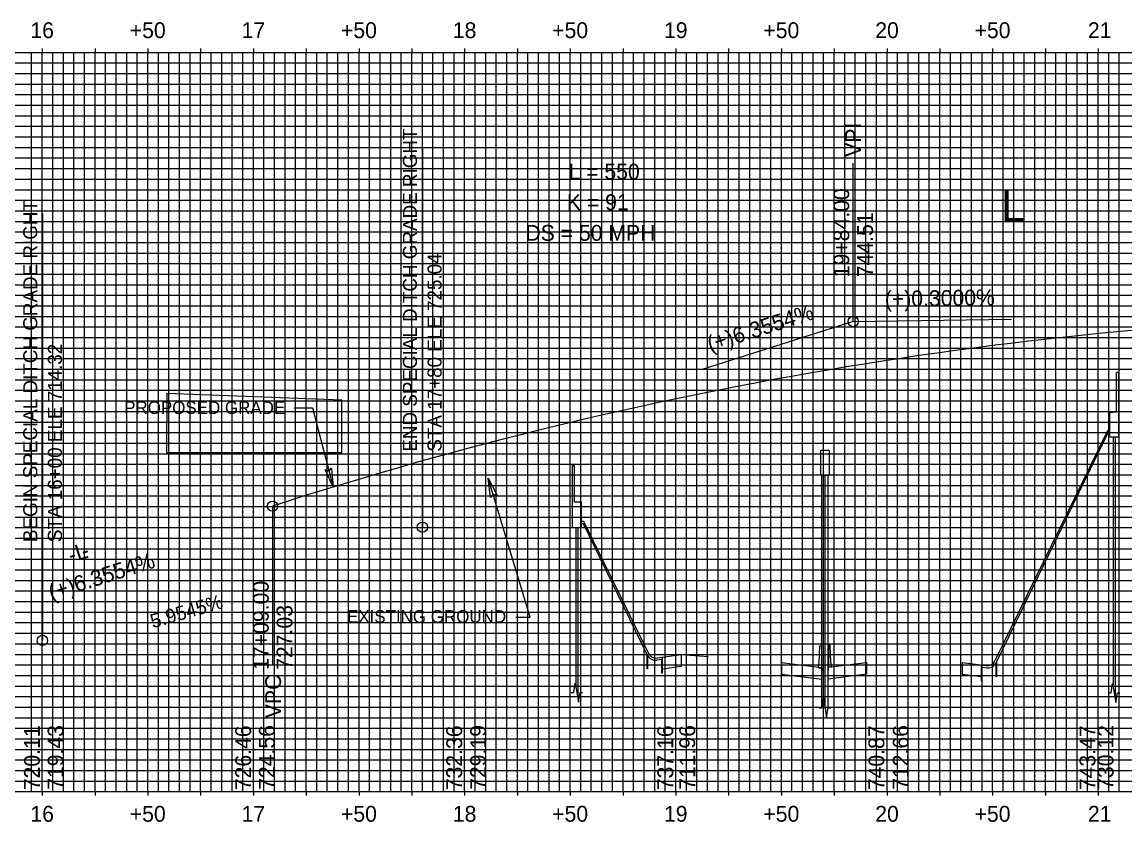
# Model space of a CAD drawing. Extents: x 273 to 1727, y 687 to 1144.
# Drawn here: x 590 to 1113, y 766 to 1144 of the extents above; entities that cross this region are included whole.
import ezdxf

# ---------------------------------------------------------------- set-up
doc = ezdxf.new("R2010")
doc.units = 0
for name, color, linetype in [('3D Cell Connection Region', 7, 'Continuous'), ('Catch Basin Box 24 Dia-Bottom CELL', 7, 'Continuous'), ('Construction Elements LEVEL', 7, 'Continuous'), ('Cut Ditch Special with Hinge Detail CELL', 7, 'Continuous'), ('Default', 7, 'Continuous'), ('Drop Inlet Box Type A 48 Dia-Bottom CELL', 7, 'Continuous'), ('Drop Inlet Box Type B 36 Dia-Bottom CELL', 7, 'Continuous'), ('Drop Inlet Grate 2 Narrow Slot and Flat Grates 840 29 36 Dia BD CELL', 7, 'Continuous'), ('Drop Inlet Grate 2 Narrow Slot and Flat Grates 840 29 36 Dia BD-Top CELL', 7, 'Continuous'), ('Drop Inlet Grate 2 Narrow Slot and Flat Grates 840 29 36 Dia TB-Top CELL', 7, 'Continuous'), ('Drop Inlet Grate 2 Wide Slot and Flat Grates 840 20 48 Dia Apron-Top CELL', 7, 'Continuous'), ('Drop Inlet Grate 2 Wide Slot and Flat Grates 840 20 TB-Top CELL', 7, 'Continuous'), ('E_NCDOT_Terrain_Model_Triangle_Vertices', 7, 'Continuous'), ('E_NCDOT_Vertical_Profile_Ground_Line', 7, 'Continuous'), ('Junction Box with Manhole 840 31 42 Dia TB-Top CELL', 7, 'Continuous'), ('Junction Box with Manhole 840 31 48 Dia CELL', 7, 'Continuous'), ('Junction Box with Manhole 840 31 66 Dia-Top CELL', 7, 'Continuous'), ('Junction Box with Manhole 840 52 Round TB 6 Feet CELL', 7, 'Continuous'), ('P_HYD_Drop_Inlet_Box_Type_B_36_Dia-Bottom_CELL', 7, 'Continuous'), ('P_NCDOT_SS_Cut_Line', 7, 'Continuous'), ('P_NCDOT_SS_Transition_Line', 7, 'Continuous')]:
    doc.layers.add(name, color=color, linetype=linetype)

msp = doc.modelspace()

# ---------------------------------------------------------------- linework, layer by layer
at = {"layer": 'Construction Elements LEVEL'}
for p, q in [((600, 780), (600, 1130)), ((650, 780), (650, 1130)), ((700, 780), (700, 1130)), ((750, 780), (750, 1130)), ((800, 780), (800, 1130)), ((850, 780), (850, 1130)), ((900, 780), (900, 1130)), ((950, 780), (950, 1130)), ((1000, 780), (1000, 1130)), ((1050, 780), (1050, 1130)), ((1100, 780), (1100, 1130)), ((517.06, 1080), (1700, 1080)), ((300, 1030), (1700, 1030)), ((300, 980), (1700, 980)), ((300, 930), (1700, 930)), ((300, 880), (1700, 880)), ((300, 830), (1700, 830)), ((300, 780), (1700, 780)), ((300, 780), (1700, 780))]:
    msp.add_line(p, q, dxfattribs=at)
at = {"layer": 'Cut Ditch Special with Hinge Detail CELL'}
for p, q in [((780, 1084.3), (780, 905.2)), ((600.08, 1053.65), (600.08, 851.6))]:
    msp.add_line(p, q, dxfattribs=at)
for centre in [(780, 905.2), (600.08, 851.6)]:
    msp.add_circle(centre, 2.43, dxfattribs=at)
at = {"layer": 'Default'}
msp.add_arc((1286.54, -872.9), 1879.03, 90.83992, 107.90043, dxfattribs=at)
at = {"layer": 'Drop Inlet Box Type A 48 Dia-Bottom CELL'}
for p, q in [((1108.7, 959.88), (1108.7, 978.45)), ((1109.7, 978.45), (1108.7, 978.45)), ((1109.7, 947.88), (1109.7, 978.45)), ((1105.45, 959.56), (1108.7, 959.88)), ((1105.45, 947.88), (1105.45, 959.56)), ((1105.45, 950.88), (1104.45, 950.88)), ((1105.45, 949.88), (1104.52, 949.88)), ((1109.7, 947.88), (1105.45, 947.88)), ((851.02, 904.98), (851.02, 934.36)), ((851.02, 934.36), (852.02, 934.36)), ((852.02, 916.98), (852.02, 934.36)), ((855.27, 916.98), (852.02, 916.98)), ((855.27, 904.98), (855.27, 916.98)), ((851.02, 904.98), (855.27, 904.98)), ((855.27, 907.98), (856.27, 907.98)), ((855.27, 906.98), (856.2, 906.98))]:
    msp.add_line(p, q, dxfattribs=at)
at = {"layer": 'Drop Inlet Box Type B 36 Dia-Bottom CELL'}
for p, q in [((984, 1002.55), (984, 1077.55)), ((984, 1002.55), (1058.99, 1003.67)), ((984, 1002.55), (912.52, 979.84)), ((984, 1002.55), (984, 1002.55)), ((719.34, 961.77), (727.98, 961.77)), ((727.98, 961.77), (737.83, 924.1)), ((831.04, 862.63), (811.2, 928.36)), ((709, 915.16), (709, 915.16)), ((709, 915.16), (709, 840.16)), ((824.2, 862.63), (831.04, 862.63))]:
    msp.add_line(p, q, dxfattribs=at)
msp.add_lwpolyline([(658.81, 940.58), (741.85, 940.58), (741.85, 965.31), (659.01, 968.57)], close=True, dxfattribs=at)
for centre in [(984, 1002.55), (709, 915.16)]:
    msp.add_circle(centre, 2.43, dxfattribs=at)
at = {"layer": 'Drop Inlet Grate 2 Narrow Slot and Flat Grates 840 29 36 Dia BD CELL'}
for centre in [(780, 905.2), (600.14, 845.14), (984, 784.98)]:
    msp.add_circle(centre, 0.05, dxfattribs=at)
at = {"layer": 'Drop Inlet Grate 2 Wide Slot and Flat Grates 840 20 48 Dia Apron-Top CELL'}
for p, q in [((969.15, 838.54), (969.15, 838.54)), ((972.15, 838.9), (972.15, 838.9))]:
    msp.add_line(p, q, dxfattribs=at)
at = {"layer": 'Drop Inlet Grate 2 Wide Slot and Flat Grates 840 20 TB-Top CELL'}
for p, q in [((967.52, 838.54), (969.02, 838.54)), ((969.11, 838.54), (969.02, 838.54)), ((969.11, 838.54), (969.15, 838.41)), ((969.15, 838.41), (969.15, 837.04)), ((972.19, 838.9), (972.15, 838.77)), ((972.15, 838.77), (972.15, 837.4)), ((972.19, 838.9), (972.27, 838.9)), ((973.77, 838.9), (972.27, 838.9))]:
    msp.add_line(p, q, dxfattribs=at)
for points in [[(967.52, 838.54), (967.52, 839.29), (967.93, 841.04), (968.2, 848.85), (968.26, 849.04), (968.96, 849.04), (969.02, 848.85), (969.02, 838.54)], [(973.77, 838.9), (973.77, 839.65), (973.37, 841.4), (973.09, 849.21), (973.03, 849.4), (972.33, 849.4), (972.27, 849.21), (972.27, 838.9)]]:
    msp.add_lwpolyline(points, dxfattribs=at)
at = {"layer": 'E_NCDOT_Terrain_Model_Triangle_Vertices'}
for p, q in [((1107.08, 947.91), (1107.08, 829.92)), ((1108.08, 947.91), (1108.08, 823.84)), ((852.65, 904.98), (852.65, 830.01)), ((853.65, 904.98), (853.65, 824.04))]:
    msp.add_line(p, q, dxfattribs=at)
at = {"layer": 'E_NCDOT_Vertical_Profile_Ground_Line'}
for p, q in [((595, 780), (595, 1130)), ((605, 780), (605, 1130)), ((610, 780), (610, 1130)), ((615, 780), (615, 1130)), ((620, 780), (620, 1130)), ((630, 780), (630, 1130)), ((635, 780), (635, 1130)), ((640, 780), (640, 1130)), ((645, 780), (645, 1130)), ((655, 780), (655, 1130)), ((660, 780), (660, 1130)), ((665, 780), (665, 1130)), ((670, 780), (670, 1130)), ((680, 780), (680, 1130)), ((685, 780), (685, 1130)), ((690, 780), (690, 1130)), ((695, 780), (695, 1130)), ((705, 780), (705, 1130)), ((710, 780), (710, 1130)), ((715, 780), (715, 1130)), ((720, 780), (720, 1130)), ((730, 780), (730, 1130)), ((735, 780), (735, 1130)), ((740, 780), (740, 1130)), ((745, 780), (745, 1130)), ((755, 780), (755, 1130)), ((760, 780), (760, 1130)), ((765, 780), (765, 1130)), ((770, 780), (770, 1130)), ((780, 780), (780, 1130)), ((785, 780), (785, 1130)), ((790, 780), (790, 1130)), ((795, 780), (795, 1130)), ((805, 780), (805, 1130)), ((810, 780), (810, 1130)), ((815, 780), (815, 1130)), ((820, 780), (820, 1130)), ((830, 780), (830, 1130)), ((835, 780), (835, 1130)), ((840, 780), (840, 1130)), ((845, 780), (845, 1130)), ((855, 780), (855, 1130)), ((860, 780), (860, 1130)), ((865, 780), (865, 1130)), ((870, 780), (870, 1130)), ((880, 780), (880, 1130)), ((885, 780), (885, 1130)), ((890, 780), (890, 1130)), ((895, 780), (895, 1130)), ((905, 780), (905, 1130)), ((910, 780), (910, 1130)), ((915, 780), (915, 1130)), ((920, 780), (920, 1130)), ((930, 780), (930, 1130)), ((935, 780), (935, 1130)), ((940, 780), (940, 1130)), ((945, 780), (945, 1130)), ((955, 780), (955, 1130)), ((960, 780), (960, 1130)), ((965, 780), (965, 1130)), ((970, 780), (970, 1130)), ((980, 780), (980, 1130)), ((985, 780), (985, 1130)), ((990, 780), (990, 1130)), ((995, 780), (995, 1130)), ((1005, 780), (1005, 1130)), ((1010, 780), (1010, 1130)), ((1015, 780), (1015, 1130)), ((1020, 780), (1020, 1130)), ((1030, 780), (1030, 1130)), ((1035, 780), (1035, 1130)), ((1040, 780), (1040, 1130)), ((1045, 780), (1045, 1130)), ((1055, 780), (1055, 1130)), ((1060, 780), (1060, 1130)), ((1065, 780), (1065, 1130)), ((1070, 780), (1070, 1130)), ((1080, 780), (1080, 1130)), ((1085, 780), (1085, 1130)), ((1090, 780), (1090, 1130)), ((1095, 780), (1095, 1130)), ((1105, 780), (1105, 1130)), ((1110, 780), (1110, 1130)), ((300, 1125), (1700, 1125)), ((300, 1120), (1700, 1120)), ((300, 1115), (1700, 1115)), ((300, 1110), (1700, 1110)), ((517.06, 1100), (1700, 1100)), ((517.06, 1095), (1700, 1095)), ((517.06, 1090), (1700, 1090)), ((517.06, 1085), (1700, 1085)), ((517.06, 1075), (1700, 1075)), ((300, 1070), (1700, 1070)), ((300, 1065), (1700, 1065)), ((300, 1060), (1700, 1060)), ((300, 1050), (1700, 1050)), ((300, 1045), (1700, 1045)), ((300, 1040), (1700, 1040)), ((300, 1035), (1700, 1035)), ((300, 1025), (1700, 1025)), ((300, 1020), (1700, 1020)), ((300, 1015), (1700, 1015)), ((300, 1010), (1700, 1010)), ((300, 1000), (1700, 1000)), ((300, 995), (1700, 995)), ((300, 990), (1700, 990)), ((300, 985), (1700, 985)), ((300, 975), (1700, 975)), ((300, 970), (1700, 970)), ((300, 965), (1700, 965)), ((300, 960), (1700, 960)), ((300, 950), (1700, 950)), ((300, 945), (1700, 945)), ((300, 940), (1700, 940)), ((300, 935), (1700, 935)), ((300, 925), (1700, 925)), ((300, 920), (1700, 920)), ((300, 915), (1700, 915)), ((300, 910), (1700, 910)), ((300, 900), (1700, 900)), ((300, 895), (1700, 895)), ((300, 890), (1700, 890)), ((300, 885), (1700, 885)), ((300, 875), (1700, 875)), ((300, 870), (1700, 870)), ((300, 865), (1700, 865)), ((300, 860), (1700, 860)), ((300, 850), (1700, 850)), ((300, 845), (1700, 845)), ((300, 840), (1700, 840)), ((300, 835), (1700, 835)), ((300, 825), (1700, 825)), ((300, 820), (1700, 820)), ((300, 815), (1700, 815)), ((300, 815), (1700, 815)), ((300, 810), (1700, 810)), ((300, 810), (1700, 810)), ((300, 800), (1700, 800)), ((300, 800), (1700, 800)), ((300, 795), (1700, 795)), ((300, 795), (1700, 795)), ((300, 790), (1700, 790)), ((300, 790), (1700, 790)), ((300, 785), (1700, 785)), ((300, 785), (1700, 785))]:
    msp.add_line(p, q, dxfattribs=at)
at = {"layer": 'Junction Box with Manhole 840 31 42 Dia TB-Top CELL'}
for points in [[(737.05, 933.2), (737.83, 924.1), (733.99, 932.45), (735.83, 931.74)], [(812.32, 919.3), (811.2, 928.36), (815.35, 920.16), (813.48, 920.8)]]:
    msp.add_lwpolyline(points, close=True, dxfattribs=at)
at = {"layer": 'Junction Box with Manhole 840 31 48 Dia CELL'}
for p, q in [((969.15, 819.69), (969.15, 929.63)), ((970.65, 819.69), (970.65, 929.63)), ((972.15, 819.69), (972.15, 929.63))]:
    msp.add_line(p, q, dxfattribs=at)
at = {"layer": 'Junction Box with Manhole 840 31 66 Dia-Top CELL'}
for p, q in [((1104.45, 950.88), (1051.1, 841.9)), ((1104.53, 949.88), (1052.03, 841.78)), ((856.2, 906.98), (886.31, 844.96)), ((856.27, 907.98), (887.07, 845.44)), ((1081.98, 903.44), (1051.86, 841.42)), ((886.31, 844.96), (886.31, 838.1)), ((886.64, 844.49), (886.64, 838.1)), ((886.64, 844.49), (887.08, 843.87)), ((893.21, 842.5), (890.86, 842.2)), ((902.54, 844.69), (891.16, 843.24)), ((893.21, 842.5), (893.21, 836.05)), ((893.54, 843.55), (893.54, 843.54)), ((893.54, 843.55), (893.54, 843.54)), ((893.54, 843.55), (893.54, 836.05)), ((915.25, 843.89), (902.54, 844.69)), ((902.54, 844.69), (902.54, 839.19)), ((969.15, 838.54), (949.99, 840.97)), ((949.99, 840.97), (949.99, 835.46)), ((972.15, 838.9), (990.37, 841.21)), ((990.37, 841.21), (990.37, 835.71)), ((1035.63, 841.15), (1047.01, 839.7)), ((1035.63, 841.15), (1035.63, 835.64)), ((1051.53, 840.95), (1051.09, 840.33)), ((1051.53, 840.95), (1051.53, 834.56)), ((1051.86, 841.42), (1051.86, 834.56)), ((886.64, 838.1), (886.31, 838.1)), ((893.54, 836.05), (893.21, 836.05)), ((902.54, 839.19), (893.54, 838.04)), ((972.15, 833.39), (990.37, 835.71)), ((1035.63, 835.64), (1044.63, 834.5)), ((1044.63, 840.01), (1044.63, 839.99)), ((1044.63, 840.01), (1044.63, 840)), ((1044.63, 840.01), (1044.63, 832.51)), ((1044.96, 838.96), (1047.32, 838.66)), ((1044.96, 838.96), (1044.96, 832.51)), ((969.15, 833.03), (949.99, 835.46)), ((1044.63, 832.51), (1044.96, 832.51)), ((1051.53, 834.56), (1051.86, 834.56))]:
    msp.add_line(p, q, dxfattribs=at)
msp.add_lwpolyline([(968.65, 941.63), (972.65, 941.63), (972.65, 929.63), (968.65, 929.63)], close=True, dxfattribs=at)
for centre, start, end in [((890.66, 847.21), 206.2193, 277.2452), ((890.35, 846.17), 215.1087, 277.2452), ((1047.52, 843.67), 262.7548, 333.7807), ((1047.82, 842.63), 262.7548, 324.8913)]:
    msp.add_arc(centre, 4, start, end, dxfattribs=at)
at = {"layer": 'Junction Box with Manhole 840 52 Round TB 6 Feet CELL'}
for points in [[(850.4, 826.92), (851.65, 826.92), (852.4, 831.42), (853.9, 822.42), (854.65, 826.92), (855.89, 826.92)], [(1104.83, 826.75), (1106.08, 826.75), (1106.83, 831.25), (1108.33, 822.25), (1109.08, 826.75), (1110.32, 826.75)], [(967.9, 819.69), (969.15, 819.69), (969.9, 824.19), (971.4, 815.19), (972.15, 819.69), (973.4, 819.69)]]:
    msp.add_lwpolyline(points, dxfattribs=at)
at = {"layer": 'P_NCDOT_SS_Cut_Line'}
for p, q in [((600, 1131.8), (600, 1130)), ((600, 780), (600, 1130)), ((625, 1131.8), (625, 1130)), ((625, 780), (625, 1130)), ((650, 1131.8), (650, 1130)), ((650, 780), (650, 1130)), ((675, 1131.8), (675, 1130)), ((675, 780), (675, 1130)), ((700, 1131.8), (700, 1130)), ((700, 780), (700, 1130)), ((725, 1131.8), (725, 1130)), ((725, 780), (725, 1130)), ((750, 1131.8), (750, 1130)), ((750, 780), (750, 1130)), ((775, 1131.8), (775, 1130)), ((775, 780), (775, 1130)), ((800, 1131.8), (800, 1130)), ((800, 780), (800, 1130)), ((825, 1131.8), (825, 1130)), ((825, 780), (825, 1130)), ((850, 1131.8), (850, 1130)), ((850, 780), (850, 1130)), ((875, 1131.8), (875, 1130)), ((875, 780), (875, 1130)), ((900, 1131.8), (900, 1130)), ((900, 780), (900, 1130)), ((925, 1131.8), (925, 1130)), ((925, 780), (925, 1130)), ((950, 1131.8), (950, 1130)), ((950, 780), (950, 1130)), ((975, 1131.8), (975, 1130)), ((975, 780), (975, 1130)), ((1000, 1131.8), (1000, 1130)), ((1000, 780), (1000, 1130)), ((1025, 1131.8), (1025, 1130)), ((1025, 780), (1025, 1130)), ((1050, 1131.8), (1050, 1130)), ((1050, 780), (1050, 1130)), ((1075, 1131.8), (1075, 1130)), ((1075, 780), (1075, 1130)), ((1100, 1131.8), (1100, 1130)), ((1100, 780), (1100, 1130)), ((300, 1105), (1700, 1105)), ((517.06, 1080), (1700, 1080)), ((300, 1055), (1700, 1055)), ((300, 1030), (1700, 1030)), ((300, 1005), (1700, 1005)), ((300, 980), (1700, 980)), ((300, 955), (1700, 955)), ((300, 930), (1700, 930)), ((300, 905), (1700, 905)), ((300, 880), (1700, 880)), ((300, 855), (1700, 855)), ((300, 830), (1700, 830)), ((300, 805), (1700, 805)), ((300, 805), (1700, 805)), ((300, 780), (1700, 780)), ((300, 780), (1700, 780)), ((600, 780), (600, 778.2)), ((625, 780), (625, 778.2)), ((650, 780), (650, 778.2)), ((675, 780), (675, 778.2)), ((700, 780), (700, 778.2)), ((725, 780), (725, 778.2)), ((750, 780), (750, 778.2)), ((775, 780), (775, 778.2)), ((800, 780), (800, 778.2)), ((825, 780), (825, 778.2)), ((850, 780), (850, 778.2)), ((875, 780), (875, 778.2)), ((900, 780), (900, 778.2)), ((925, 780), (925, 778.2)), ((950, 780), (950, 778.2)), ((975, 780), (975, 778.2)), ((1000, 780), (1000, 778.2)), ((1025, 780), (1025, 778.2)), ((1050, 780), (1050, 778.2)), ((1075, 780), (1075, 778.2)), ((1100, 780), (1100, 778.2))]:
    msp.add_line(p, q, dxfattribs=at)
at = {"layer": 'P_NCDOT_SS_Transition_Line'}
for p, q in [((300, 1130), (1700, 1130)), ((300, 780), (1700, 780))]:
    msp.add_line(p, q, dxfattribs=at)

# ---------------------------------------------------------------- texts
at = {"layer": '3D Cell Connection Region'}
for s, p in [('L = 550', (849.18, 1069.79)), ('K = 91', (848.41, 1055.29)), ('DS = 50 MPH', (828.79, 1040.78))]:
    msp.add_text(s, height=7.5, rotation=0.0157, dxfattribs=at).set_placement(p)
msp.add_text('L', height=15, dxfattribs=at).set_placement((1054.12, 1049.86))
at = {"layer": 'Catch Basin Box 24 Dia-Bottom CELL'}
for s, p in [('16', (594.41, 1136.75)), ('+50', (641.46, 1136.75)), ('17', (694.41, 1136.75)), ('+50', (741.46, 1136.75)), ('18', (794.41, 1136.75)), ('+50', (841.46, 1136.75)), ('19', (894.41, 1136.75)), ('+50', (941.46, 1136.75)), ('20', (994.43, 1136.75)), ('+50', (1041.46, 1136.75)), ('21', (1095.14, 1136.75)), ('16', (594.41, 765.75)), ('+50', (641.46, 765.75)), ('17', (694.41, 765.75)), ('+50', (741.46, 765.75)), ('18', (794.41, 765.75)), ('+50', (841.46, 765.75)), ('19', (894.41, 765.75)), ('+50', (941.46, 765.75)), ('20', (994.43, 765.75)), ('+50', (1041.46, 765.75)), ('21', (1095.14, 765.75))]:
    msp.add_text(s, height=7.5, dxfattribs=at).set_placement(p)
at = {"layer": 'Cut Ditch Special with Hinge Detail CELL'}
for s, rotation, p in [('END SPECIAL DITCH GRADE RIGHT', 90, (777.44, 940.94)), ('BEGIN SPECIAL DITCH GRADE RIGHT', 90, (597.67, 898.15)), ('STA 17+80 ELE 725.04', 90, (789.11, 940.94)), ('STA 16+00 ELE 714.32', 90, (609.34, 898.15)), ('5.9545%', 16.1675, (652.34, 857.26))]:
    msp.add_text(s, height=6.665, rotation=rotation, dxfattribs=at).set_placement(p)
at = {"layer": 'Drop Inlet Box Type B 36 Dia-Bottom CELL'}
for s, rotation, p in [('VPI', 90, (987.75, 1080.55)), ('19+84.00', 90, (982.12, 1023.55)), ('744.51', 90, (993.37, 1023.55)), ('(+)0.3000%', 0.8594, (999, 1009.53)), ('(+)6.3554%', 17.6286, (916.3, 988.12)), ('17+09.00', 90, (707.24, 837.67)), ('727.03', 90, (718.49, 837.67)), ('VPC', 90, (713.09, 814.77))]:
    msp.add_text(s, height=7.5, rotation=rotation, dxfattribs=at).set_placement(p)
for s, p in [('PROPOSED GRADE', (638.81, 958.81)), ('EXISTING GROUND', (744.31, 859.92))]:
    msp.add_text(s, height=6, dxfattribs=at).set_placement(p)
at = {"layer": 'Drop Inlet Grate 2 Narrow Slot and Flat Grates 840 29 36 Dia BD-Top CELL'}
for s, p in [('719.43', (610.08, 780.84)), ('724.56', (710.12, 780.84)), ('729.19', (810.14, 780.84)), ('711.96', (909.17, 780.84)), ('712.66', (1010.23, 780.84)), ('730.12', (1107.24, 780.84))]:
    msp.add_text(s, height=7.5, rotation=90, dxfattribs=at).set_placement(p)
at = {"layer": 'Drop Inlet Grate 2 Narrow Slot and Flat Grates 840 29 36 Dia TB-Top CELL'}
for s, p in [('L', (616.93, 889.27)), ('-', (619.7, 890.15)), ('(+)6.3554%', (604.36, 870.49)), ('-', (613.61, 888.22))]:
    msp.add_text(s, height=7.5, rotation=17.6286, dxfattribs=at).set_placement(p)
at = {"layer": 'P_HYD_Drop_Inlet_Box_Type_B_36_Dia-Bottom_CELL'}
for s, p in [('720.11', (598.89, 780.67)), ('726.46', (698.89, 780.67)), ('732.36', (798.82, 780.67)), ('737.16', (898.76, 780.67)), ('740.87', (998.71, 780.67)), ('743.47', (1098.68, 780.67))]:
    msp.add_text(s, height=7.5, rotation=90, dxfattribs=at).set_placement(p)

doc.saveas('drawing.dxf')
